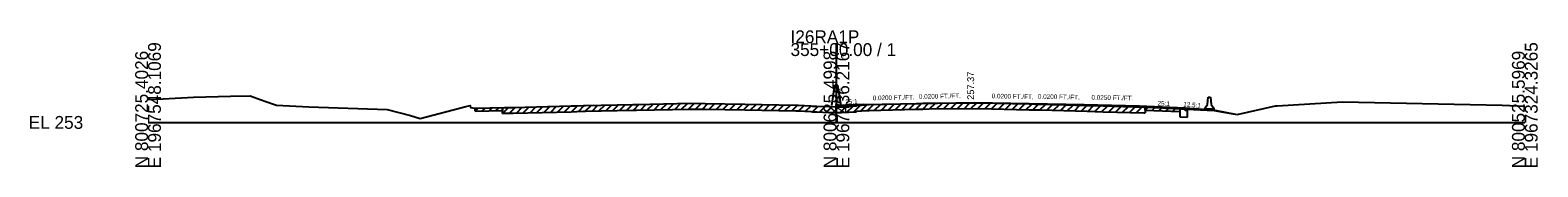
# Model space of a CAD drawing. Extents: x -26 to 304, y -10 to 7527.
# Drawn here: x -25.7 to 302.8, y 2490.3 to 2520.1 of the extents above; entities that cross this region are included whole.
import ezdxf

# ---------------------------------------------------------------- set-up
doc = ezdxf.new("R2010")
doc.units = 0
for name, color, linetype in [('Default', 7, 'Continuous'), ('RD_GPK_XS_Cell', 7, 'Continuous'), ('RD_XS_Base', 7, 'Continuous'), ('RD_XS_Box', 7, 'Continuous'), ('RD_XS_EarthShd', 7, 'Continuous'), ('RD_XS_ExGround', 7, 'Continuous'), ('RD_XS_ExPaveRet', 7, 'Continuous'), ('RD_XS_Misc_Line', 7, 'Continuous'), ('RD_XS_Pave', 7, 'Continuous'), ('RD_XS_PaveShd', 7, 'Continuous'), ('RD_XS_TX_Elev_EX', 7, 'Continuous'), ('RD_XS_TX_Elev_PR', 7, 'Continuous'), ('RD_XS_TX_Misc', 7, 'Continuous'), ('RD_XS_TX_MkPT', 7, 'Continuous'), ('RD_XS_TX_Profile', 7, 'Continuous'), ('RD_XS_TX_Station', 7, 'Continuous')]:
    doc.layers.add(name, color=color, linetype=linetype)

msp = doc.modelspace()

# ---------------------------------------------------------------- linework, layer by layer
at = {"layer": 'Default'}
for p, q in [((230.24, 2503.1), (230.83, 2503.94)), ((230.83, 2503.94), (230.99, 2505.52)), ((230.99, 2505.52), (231.49, 2505.52)), ((231.49, 2505.52), (231.66, 2503.94)), ((231.66, 2503.94), (232.24, 2503.1)), ((230.24, 2502.85), (230.24, 2503.1)), ((232.24, 2502.85), (230.24, 2502.85)), ((232.24, 2503.1), (232.24, 2502.85))]:
    msp.add_line(p, q, dxfattribs=at)
at = {"layer": 'RD_GPK_XS_Cell'}
for p, q in [((150, 2500), (150, 2517.27)), ((0, 2500), (150, 2500)), ((150, 2500), (300, 2500))]:
    msp.add_line(p, q, dxfattribs=at)
at = {"layer": 'RD_XS_Base'}
for p, q in [((150, 2503.42), (150, 2503.65)), ((224.86, 2501.2), (226.5, 2501.13)), ((226, 2502.63), (226, 2503.19)), ((226.5, 2502.61), (226, 2502.63)), ((226.5, 2501.13), (226.5, 2502.61))]:
    msp.add_line(p, q, dxfattribs=at)
at = {"layer": 'RD_XS_Box'}
for p, q in [((228, 2503.03), (232.49, 2502.67)), ((232.49, 2502.67), (237.35, 2501.72))]:
    msp.add_line(p, q, dxfattribs=at)
at = {"layer": 'RD_XS_EarthShd'}
for p, q in [((149, 2503.67), (149.67, 2508.15)), ((150, 2508.15), (149.67, 2508.15)), ((150, 2508.15), (150.33, 2508.15)), ((151, 2503.67), (150.33, 2508.15)), ((226, 2503.19), (228, 2503.03))]:
    msp.add_line(p, q, dxfattribs=at)
at = {"layer": 'RD_XS_ExGround'}
msp.add_lwpolyline([(0, 2504.97), (3.29, 2505.14), (9.9, 2505.51), (17.96, 2505.7), (22.27, 2505.76), (25.48, 2504.66), (28.02, 2503.78), (35.06, 2503.43), (52.09, 2502.84), (57.15, 2501.47), (59.32, 2500.84), (69.26, 2503.44), (70.17, 2503.68), (70.27, 2503.23), (71.3, 2503.1), (77.64, 2503.23), (78.27, 2503.25), (79.58, 2503.28), (92.19, 2503.58), (93.43, 2503.62), (94.9, 2503.67), (95.3, 2503.68), (105.63, 2503.92), (106.42, 2503.93), (118.21, 2504.16), (121.37, 2504.12), (130.07, 2504), (141.14, 2503.76), (141.76, 2503.74), (144.43, 2503.64), (144.73, 2503.54), (145.71, 2503.52), (148.31, 2503.44), (150, 2503.42), (150.74, 2503.41), (151.08, 2503.41), (154.29, 2503.59), (154.48, 2503.7), (156.53, 2503.83), (157.16, 2503.87), (167.4, 2504.13), (168.81, 2504.17), (170.24, 2504.18), (181.02, 2504.27), (192.02, 2504.02), (193.22, 2504), (194.44, 2503.97), (204.61, 2503.7), (208.14, 2503.59), (216.97, 2503.33), (221.02, 2503.16), (224.86, 2502.97), (227.8, 2502.82), (232.32, 2502.56), (234.37, 2502.21), (237.35, 2501.72), (245.7, 2503.62), (246.07, 2503.64), (260.3, 2504.48), (295.05, 2503.74), (300, 2503.56)], dxfattribs=at)
at = {"layer": 'RD_XS_ExPaveRet'}
for p, q in [((71.3, 2502.48), (71.3, 2503.1)), ((71.3, 2502.48), (77.25, 2502.6)), ((77.25, 2501.97), (77.25, 2503.22)), ((77.25, 2503.22), (77.25, 2502.6)), ((77.25, 2501.97), (77.64, 2501.98)), ((77.64, 2501.98), (78.27, 2502)), ((78.27, 2502), (79.58, 2502.03)), ((79.58, 2502.03), (92.19, 2502.33)), ((92.19, 2502.33), (93.43, 2502.37)), ((93.43, 2502.37), (94.9, 2502.42)), ((94.9, 2502.42), (95.3, 2502.43)), ((95.3, 2502.43), (105.63, 2502.67)), ((105.63, 2502.67), (106.42, 2502.68)), ((106.42, 2502.68), (118.21, 2502.91)), ((118.21, 2502.91), (121.37, 2502.87)), ((121.37, 2502.87), (130.07, 2502.75)), ((130.07, 2502.75), (141.14, 2502.51)), ((141.14, 2502.51), (141.76, 2502.49)), ((141.76, 2502.49), (144.43, 2502.39)), ((144.43, 2502.39), (144.73, 2502.29)), ((144.73, 2502.29), (145.71, 2502.27)), ((145.71, 2502.27), (148.31, 2502.19)), ((148.31, 2502.19), (150, 2502.17)), ((150, 2502.17), (150.74, 2502.16)), ((150.74, 2502.16), (151.08, 2502.16)), ((151.08, 2502.16), (154.29, 2502.34)), ((154.29, 2502.34), (154.48, 2502.45)), ((154.48, 2502.45), (156.53, 2502.58)), ((156.53, 2502.58), (157.16, 2502.62)), ((157.16, 2502.62), (167.4, 2502.88)), ((167.4, 2502.88), (168.81, 2502.92)), ((168.81, 2502.92), (170.24, 2502.93)), ((170.24, 2502.93), (181.02, 2503.02)), ((181.02, 2503.02), (192.02, 2502.77)), ((192.02, 2502.77), (193.22, 2502.75)), ((193.22, 2502.75), (194.44, 2502.72)), ((194.44, 2502.72), (204.61, 2502.45)), ((204.61, 2502.45), (208.14, 2502.34)), ((208.14, 2502.34), (216.97, 2502.08)), ((216.97, 2502.08), (217.3, 2502.07)), ((217.3, 2503.32), (217.3, 2502.07)), ((217.3, 2502.69), (217.3, 2503.32)), ((217.3, 2502.69), (221.02, 2502.53)), ((221.02, 2502.53), (224.86, 2502.35)), ((224.86, 2502.97), (224.86, 2502.35))]:
    msp.add_line(p, q, dxfattribs=at)
at = {"layer": 'RD_XS_Misc_Line'}
for p, q in [((84.75, 2502.16), (86.03, 2503.44)), ((86.25, 2502.19), (87.53, 2503.47)), ((87.75, 2502.23), (89.03, 2503.51)), ((89.25, 2502.26), (90.54, 2503.54)), ((90.76, 2502.3), (92.04, 2503.58)), ((92.26, 2502.34), (93.55, 2503.63)), ((93.76, 2502.38), (95.05, 2503.67)), ((95.26, 2502.43), (96.54, 2503.71)), ((96.76, 2502.46), (98.04, 2503.74)), ((98.26, 2502.5), (99.54, 2503.78)), ((99.76, 2502.53), (101.04, 2503.81)), ((101.26, 2502.57), (102.54, 2503.84)), ((102.76, 2502.6), (104.04, 2503.88)), ((104.27, 2502.63), (105.55, 2503.91)), ((105.77, 2502.67), (107.04, 2503.95)), ((107.27, 2502.7), (108.54, 2503.97)), ((108.77, 2502.73), (110.04, 2504)), ((110.27, 2502.76), (111.55, 2504.03)), ((111.77, 2502.79), (113.05, 2504.06)), ((113.27, 2502.82), (114.55, 2504.09)), ((114.77, 2502.84), (116.05, 2504.12)), ((116.27, 2502.87), (117.55, 2504.15)), ((117.78, 2502.9), (119.02, 2504.15)), ((119.28, 2502.9), (120.51, 2504.13)), ((120.78, 2502.88), (122.01, 2504.11)), ((122.28, 2502.86), (123.51, 2504.09)), ((123.78, 2502.83), (125.01, 2504.07)), ((125.28, 2502.81), (126.51, 2504.05)), ((126.78, 2502.79), (128.02, 2504.02)), ((128.28, 2502.77), (129.52, 2504)), ((129.78, 2502.75), (131.01, 2503.97)), ((131.28, 2502.72), (132.51, 2503.94)), ((132.79, 2502.69), (134.01, 2503.91)), ((134.29, 2502.65), (135.51, 2503.88)), ((135.79, 2502.62), (137.01, 2503.85)), ((137.29, 2502.59), (138.51, 2503.81)), ((138.79, 2502.56), (140.01, 2503.78)), ((140.29, 2502.53), (141.52, 2503.75)), ((141.79, 2502.49), (143, 2503.7)), ((143.29, 2502.44), (144.48, 2503.63)), ((144.79, 2502.29), (146.01, 2503.51)), ((146.3, 2502.25), (147.51, 2503.47)), ((147.8, 2502.21), (149.02, 2503.43)), ((150.8, 2502.16), (152.11, 2503.47)), ((152.3, 2502.23), (153.62, 2503.55)), ((153.8, 2502.31), (155.24, 2503.75)), ((155.3, 2502.5), (156.64, 2503.84)), ((156.8, 2502.6), (158.1, 2503.89)), ((158.3, 2502.65), (159.59, 2503.93)), ((159.81, 2502.69), (161.09, 2503.97)), ((161.31, 2502.73), (162.59, 2504.01)), ((162.81, 2502.77), (164.09, 2504.05)), ((164.31, 2502.8), (165.59, 2504.09)), ((165.81, 2502.84), (167.09, 2504.13)), ((167.31, 2502.88), (168.6, 2504.17)), ((168.81, 2502.92), (170.07, 2504.18)), ((170.31, 2502.93), (171.57, 2504.19)), ((171.81, 2502.94), (173.08, 2504.2)), ((173.32, 2502.96), (174.58, 2504.22)), ((174.82, 2502.97), (176.08, 2504.23)), ((176.32, 2502.98), (177.58, 2504.24)), ((177.82, 2502.99), (179.08, 2504.25)), ((179.32, 2503.01), (180.58, 2504.27)), ((180.82, 2503.02), (182.05, 2504.25)), ((182.32, 2502.99), (183.55, 2504.21)), ((183.82, 2502.96), (185.05, 2504.18)), ((185.32, 2502.92), (186.55, 2504.14)), ((186.83, 2502.89), (188.05, 2504.11)), ((188.33, 2502.85), (189.55, 2504.08)), ((189.83, 2502.82), (191.05, 2504.04)), ((191.33, 2502.79), (192.55, 2504.01)), ((192.83, 2502.76), (194.05, 2503.98)), ((194.33, 2502.72), (195.55, 2503.94)), ((195.83, 2502.68), (197.05, 2503.9)), ((197.33, 2502.64), (198.55, 2503.86)), ((198.83, 2502.6), (200.05, 2503.82)), ((200.33, 2502.56), (201.55, 2503.78)), ((201.84, 2502.52), (203.05, 2503.74)), ((203.34, 2502.48), (204.56, 2503.7)), ((204.84, 2502.44), (206.05, 2503.65)), ((206.34, 2502.39), (207.55, 2503.61)), ((207.84, 2502.35), (209.06, 2503.56)), ((209.34, 2502.3), (210.56, 2503.52)), ((210.84, 2502.26), (212.06, 2503.48)), ((212.34, 2502.22), (213.56, 2503.43)), ((71.3, 2502.48), (71.94, 2503.11)), ((72.81, 2502.51), (73.44, 2503.14)), ((74.31, 2502.54), (74.95, 2503.17)), ((75.81, 2502.57), (76.45, 2503.21)), ((77.25, 2501.97), (78.53, 2503.25)), ((78.75, 2502.01), (80.03, 2503.29)), ((80.25, 2502.05), (81.53, 2503.33)), ((81.75, 2502.08), (83.03, 2503.37)), ((83.25, 2502.12), (84.53, 2503.4)), ((149.3, 2502.18), (150.53, 2503.41)), ((213.84, 2502.17), (215.06, 2503.39)), ((215.35, 2502.13), (216.56, 2503.34)), ((217.3, 2502.69), (217.9, 2503.29)), ((218.81, 2502.63), (219.41, 2503.23)), ((220.31, 2502.56), (220.91, 2503.16)), ((221.81, 2502.49), (222.41, 2503.09)), ((223.31, 2502.42), (223.91, 2503.02))]:
    msp.add_line(p, q, dxfattribs=at)
at = {"layer": 'RD_XS_Pave'}
for p, q in [((156, 2503.89), (180, 2504.37)), ((180, 2504.37), (204, 2503.89)), ((204, 2503.89), (216, 2503.59))]:
    msp.add_line(p, q, dxfattribs=at)
at = {"layer": 'RD_XS_PaveShd'}
for p, q in [((156, 2503.89), (150, 2503.65)), ((216, 2503.59), (226, 2503.19))]:
    msp.add_line(p, q, dxfattribs=at)
at = {"layer": 'RD_XS_TX_Elev_PR'}
for p, q in [((150, 2503.42), (150.74, 2503.41)), ((151.08, 2503.41), (154.29, 2503.59)), ((154.29, 2503.59), (154.48, 2503.7)), ((154.48, 2503.7), (156.53, 2503.83)), ((156.53, 2503.83), (157.16, 2503.87)), ((157.16, 2503.87), (167.4, 2504.13)), ((167.4, 2504.13), (168.81, 2504.17)), ((168.81, 2504.17), (170.24, 2504.18)), ((170.24, 2504.18), (181.02, 2504.27)), ((181.02, 2504.27), (192.02, 2504.02)), ((192.02, 2504.02), (193.22, 2504)), ((193.22, 2504), (194.44, 2503.97)), ((194.44, 2503.97), (204.61, 2503.7)), ((204.61, 2503.7), (208.14, 2503.59)), ((208.14, 2503.59), (216.97, 2503.33)), ((150.74, 2503.41), (151.08, 2503.41)), ((216.97, 2503.33), (217.3, 2503.32)), ((217.3, 2503.32), (221.02, 2503.16)), ((221.02, 2503.16), (224.86, 2502.97)), ((224.86, 2502.97), (224.86, 2501.2))]:
    msp.add_line(p, q, dxfattribs=at)

# ---------------------------------------------------------------- texts
at = {"layer": 'RD_GPK_XS_Cell'}
for s, p in [('I26RA1P', (140, 2517.27)), ('355+00.00 / 1', (140, 2514.47)), ('EL 253', (-26, 2498.6))]:
    msp.add_text(s, height=2.8, dxfattribs=at).set_placement(p)
for s, p in [('E 1967548.1069', (2.8, 2490)), ('E 1967436.2167', (152.8, 2490)), ('E 1967324.3265', (302.8, 2490)), ('N 800725.4026', (0, 2490)), ('N 800625.4998', (150, 2490)), ('N 800525.5969', (300, 2490))]:
    msp.add_text(s, height=2.8, rotation=90, dxfattribs=at).set_placement(p)
at = {"layer": 'RD_XS_TX_Elev_EX'}
msp.add_text('256.42', height=1, rotation=90, dxfattribs=at).set_placement((151, 2503.42))
at = {"layer": 'RD_XS_TX_Misc'}
msp.add_text('12.5:1', height=1, rotation=355.4261, dxfattribs=at).set_placement((225.54, 2503.48))
at = {"layer": 'RD_XS_TX_MkPT'}
for rotation, p in [(2.2906, (151.94, 2503.98)), (357.7094, (219.96, 2503.68))]:
    msp.add_text('25:1', height=1, rotation=rotation, dxfattribs=at).set_placement(p)
at = {"layer": 'RD_XS_TX_Profile'}
for s, rotation, p in [('0.0200 FT./FT.', 1.1458, (157.92, 2504.82)), ('0.0200 FT./FT.', 1.1458, (167.98, 2505.13)), ('0.0200 FT./FT.', 358.5679, (183.83, 2505.28)), ('0.0200 FT./FT.', 358.8542, (193.89, 2505.17)), ('0.0250 FT./FT.', 358.8542, (205.57, 2504.98))]:
    msp.add_text(s, height=1, rotation=rotation, dxfattribs=at).set_placement(p)
at = {"layer": 'RD_XS_TX_Station'}
msp.add_text(' 257.37', height=1.5, rotation=90, dxfattribs=at).set_placement((180, 2504.37))

doc.saveas('drawing.dxf')
